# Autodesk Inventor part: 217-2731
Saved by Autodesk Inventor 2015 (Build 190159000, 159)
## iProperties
Created: 2014-11
Part Number: 217-2731
Material: Generic
Document SubType Name: Modeling
Designer: User
Density: 1 g/cm^3
Appearance: Default
Author: User
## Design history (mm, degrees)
node "217-2731.ipt1"
node "Revolve1"
node "Base1"
